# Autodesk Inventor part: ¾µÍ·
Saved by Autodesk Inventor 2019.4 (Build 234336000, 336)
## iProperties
Created: 2020-05
Part Number: ¾µÍ·
Material: Generic
Document SubType Name: Modeling
Designer: Administrator
Density: 1 g/cm^3
Appearance: Default
Title: ¾µÍ·
Author: Administrator
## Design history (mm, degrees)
feature "Body1"
body "Solid1"
